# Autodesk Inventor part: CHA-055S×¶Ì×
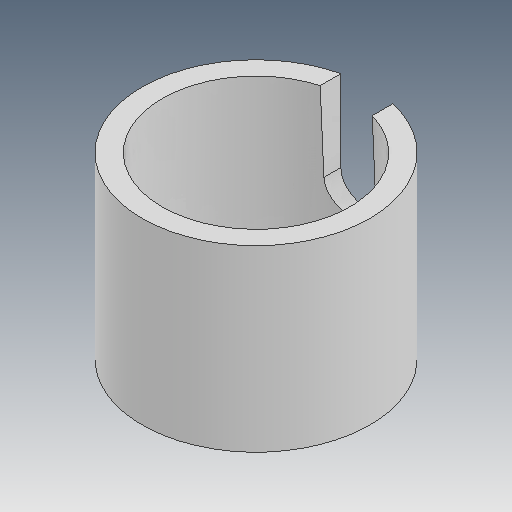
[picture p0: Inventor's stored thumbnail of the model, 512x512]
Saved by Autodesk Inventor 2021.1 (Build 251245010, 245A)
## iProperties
Created: 2019-05
Part Number: CHA-055S×¶Ì×
Material: Ogólny
Document SubType Name: Modeling
Designer: user
Density: 1 g/cm^3
Appearance: Domyślna
Author: user
Revision Number: ÈÎºÎ
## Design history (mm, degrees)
feature "ÊäÈë1"
node "Bryła1"
